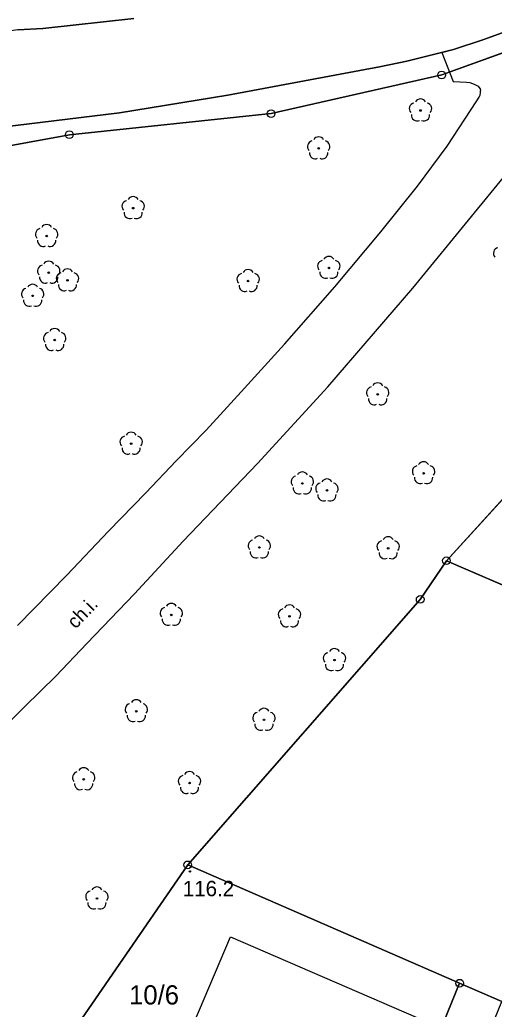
# Model space of a CAD drawing. Extents: x 6434771 to 6436222, y 5663454 to 5664782.
# Drawn here: x 6435621.2 to 6435652.1, y 5663799.7 to 5663864.1 of the extents above; entities that cross this region are included whole.
import ezdxf

# ---------------------------------------------------------------- set-up
doc = ezdxf.new("R2010")
doc.units = 0
for name, color, linetype in [('Warstwa 1', 7, 'Continuous'), ('Warstwa 10', 7, 'Continuous'), ('Warstwa 11', 7, 'Continuous'), ('Warstwa 13', 7, 'Continuous'), ('Warstwa 15', 7, 'Continuous'), ('Warstwa 18', 7, 'Continuous'), ('Warstwa 6', 7, 'Continuous'), ('Warstwa 8', 7, 'Continuous'), ('Warstwa 9', 7, 'Continuous')]:
    doc.layers.add(name, color=color, linetype=linetype)

msp = doc.modelspace()

# ---------------------------------------------------------------- linework, layer by layer
at = {"layer": 'Warstwa 1'}
for p, q in [((6435648.655, 5663860.497), (6435657.302, 5663863.623)), ((6435648.655, 5663860.497), (6435657.302, 5663863.623)), ((6435637.544, 5663857.981), (6435648.655, 5663860.497)), ((6435637.544, 5663857.981), (6435648.655, 5663860.497)), ((6435624.408, 5663856.609), (6435637.544, 5663857.981)), ((6435624.408, 5663856.609), (6435637.544, 5663857.981)), ((6435613.214, 5663854.564), (6435624.408, 5663856.609)), ((6435613.214, 5663854.564), (6435624.408, 5663856.609)), ((6435648.964, 5663828.871), (6435656.848, 5663837.517)), ((6435648.964, 5663828.871), (6435656.848, 5663837.517)), ((6435647.254, 5663826.352), (6435648.964, 5663828.871)), ((6435647.254, 5663826.352), (6435648.964, 5663828.871)), ((6435648.964, 5663828.871), (6435679.775, 5663815.599)), ((6435648.964, 5663828.871), (6435679.775, 5663815.599)), ((6435632.116, 5663809.073), (6435647.254, 5663826.352)), ((6435632.116, 5663809.073), (6435647.254, 5663826.352)), ((6435621.643, 5663793.868), (6435632.116, 5663809.073)), ((6435621.643, 5663793.868), (6435632.116, 5663809.073)), ((6435632.116, 5663809.073), (6435649.824, 5663801.369)), ((6435632.116, 5663809.073), (6435649.824, 5663801.369)), ((6435643.218, 5663785.168), (6435649.824, 5663801.369)), ((6435643.218, 5663785.168), (6435649.824, 5663801.369)), ((6435649.824, 5663801.369), (6435652.579, 5663800.176)), ((6435649.824, 5663801.369), (6435652.579, 5663800.176))]:
    msp.add_line(p, q, dxfattribs=at)
at = {"layer": 'Warstwa 10'}
for centre in [(6435648.655, 5663860.497), (6435637.544, 5663857.981), (6435624.408, 5663856.609), (6435648.964, 5663828.871), (6435648.964, 5663828.871), (6435647.254, 5663826.352), (6435647.254, 5663826.352), (6435632.116, 5663809.073), (6435632.116, 5663809.073), (6435649.824, 5663801.369)]:
    msp.add_circle(centre, 0.25, dxfattribs=at)
at = {"layer": 'Warstwa 11'}
for centre in [(6435647.275, 5663858.188), (6435640.643, 5663855.718), (6435628.562, 5663851.827), (6435622.931, 5663850.014), (6435641.308, 5663847.937), (6435623.064, 5663847.627), (6435624.285, 5663847.129), (6435636.049, 5663847.082), (6435622.019, 5663846.121), (6435623.454, 5663843.242), (6435644.487, 5663839.702), (6435628.431, 5663836.492), (6435647.474, 5663834.568), (6435639.581, 5663833.905), (6435641.18, 5663833.45), (6435636.78, 5663829.737), (6435645.169, 5663829.681), (6435631.048, 5663825.345), (6435638.746, 5663825.253), (6435641.672, 5663822.402), (6435628.769, 5663819.074), (6435637.081, 5663818.513), (6435625.342, 5663814.642), (6435632.235, 5663814.399), (6435626.203, 5663806.884)]:
    msp.add_circle(centre, 0.05, dxfattribs=at)
for centre, start, end in [((6435647.275, 5663858.563), 30.14713, 149.85287), ((6435646.918, 5663858.304), 102.14713, 221.85287), ((6435647.632, 5663858.304), 318.14713, 77.85287), ((6435647.055, 5663857.885), 174.14713, 293.85287), ((6435647.495, 5663857.885), 246.14713, 5.85287), ((6435640.286, 5663855.834), 102.14713, 221.85287), ((6435640.643, 5663856.093), 30.14713, 149.85287), ((6435641, 5663855.834), 318.14713, 77.85287), ((6435640.423, 5663855.415), 174.14713, 293.85287), ((6435640.863, 5663855.415), 246.14713, 5.85287), ((6435628.562, 5663852.202), 30.14713, 149.85287), ((6435628.205, 5663851.943), 102.14713, 221.85287), ((6435628.919, 5663851.943), 318.14713, 77.85287), ((6435628.342, 5663851.524), 174.14713, 293.85287), ((6435628.782, 5663851.524), 246.14713, 5.85287), ((6435622.574, 5663850.13), 102.14713, 221.85287), ((6435622.931, 5663850.389), 30.14713, 149.85287), ((6435623.288, 5663850.13), 318.14713, 77.85287), ((6435622.711, 5663849.711), 174.14713, 293.85287), ((6435623.151, 5663849.711), 246.14713, 5.85287), ((6435652.396, 5663848.88), 102.14713, 221.85287), ((6435641.308, 5663848.312), 30.14713, 149.85287), ((6435622.707, 5663847.743), 102.14713, 221.85287), ((6435623.064, 5663848.002), 30.14713, 149.85287), ((6435623.421, 5663847.743), 318.14713, 77.85287), ((6435624.285, 5663847.504), 30.14713, 149.85287), ((6435636.049, 5663847.457), 30.14713, 149.85287), ((6435640.951, 5663848.053), 102.14713, 221.85287), ((6435641.665, 5663848.053), 318.14713, 77.85287), ((6435622.844, 5663847.324), 174.14713, 293.85287), ((6435623.284, 5663847.324), 246.14713, 5.85287), ((6435623.928, 5663847.245), 102.14713, 221.85287), ((6435624.642, 5663847.245), 318.14713, 77.85287), ((6435635.692, 5663847.198), 102.14713, 221.85287), ((6435636.406, 5663847.198), 318.14713, 77.85287), ((6435641.088, 5663847.634), 174.14713, 293.85287), ((6435641.528, 5663847.634), 246.14713, 5.85287), ((6435621.662, 5663846.237), 102.14713, 221.85287), ((6435622.019, 5663846.496), 30.14713, 149.85287), ((6435622.376, 5663846.237), 318.14713, 77.85287), ((6435624.065, 5663846.826), 174.14713, 293.85287), ((6435624.505, 5663846.826), 246.14713, 5.85287), ((6435635.829, 5663846.779), 174.14713, 293.85287), ((6435636.269, 5663846.779), 246.14713, 5.85287), ((6435621.799, 5663845.818), 174.14713, 293.85287), ((6435622.239, 5663845.818), 246.14713, 5.85287), ((6435623.454, 5663843.617), 30.14713, 149.85287), ((6435623.097, 5663843.358), 102.14713, 221.85287), ((6435623.811, 5663843.358), 318.14713, 77.85287), ((6435623.234, 5663842.939), 174.14713, 293.85287), ((6435623.674, 5663842.939), 246.14713, 5.85287), ((6435644.13, 5663839.818), 102.14713, 221.85287), ((6435644.487, 5663840.077), 30.14713, 149.85287), ((6435644.844, 5663839.818), 318.14713, 77.85287), ((6435644.267, 5663839.399), 174.14713, 293.85287), ((6435644.707, 5663839.399), 246.14713, 5.85287), ((6435628.074, 5663836.608), 102.14713, 221.85287), ((6435628.431, 5663836.867), 30.14713, 149.85287), ((6435628.788, 5663836.608), 318.14713, 77.85287), ((6435628.211, 5663836.189), 174.14713, 293.85287), ((6435628.651, 5663836.189), 246.14713, 5.85287), ((6435647.117, 5663834.684), 102.14713, 221.85287), ((6435647.474, 5663834.943), 30.14713, 149.85287), ((6435647.831, 5663834.684), 318.14713, 77.85287), ((6435639.224, 5663834.021), 102.14713, 221.85287), ((6435639.581, 5663834.28), 30.14713, 149.85287), ((6435639.938, 5663834.021), 318.14713, 77.85287), ((6435647.254, 5663834.265), 174.14713, 293.85287), ((6435647.694, 5663834.265), 246.14713, 5.85287), ((6435639.361, 5663833.602), 174.14713, 293.85287), ((6435639.801, 5663833.602), 246.14713, 5.85287), ((6435640.823, 5663833.566), 102.14713, 221.85287), ((6435641.18, 5663833.825), 30.14713, 149.85287), ((6435641.537, 5663833.566), 318.14713, 77.85287), ((6435640.96, 5663833.147), 174.14713, 293.85287), ((6435641.4, 5663833.147), 246.14713, 5.85287), ((6435636.78, 5663830.112), 30.14713, 149.85287), ((6435645.169, 5663830.056), 30.14713, 149.85287), ((6435636.423, 5663829.853), 102.14713, 221.85287), ((6435637.137, 5663829.853), 318.14713, 77.85287), ((6435644.812, 5663829.797), 102.14713, 221.85287), ((6435645.526, 5663829.797), 318.14713, 77.85287), ((6435636.56, 5663829.434), 174.14713, 293.85287), ((6435637, 5663829.434), 246.14713, 5.85287), ((6435644.949, 5663829.378), 174.14713, 293.85287), ((6435645.389, 5663829.378), 246.14713, 5.85287), ((6435631.048, 5663825.72), 30.14713, 149.85287), ((6435638.746, 5663825.628), 30.14713, 149.85287), ((6435630.691, 5663825.461), 102.14713, 221.85287), ((6435631.405, 5663825.461), 318.14713, 77.85287), ((6435638.389, 5663825.369), 102.14713, 221.85287), ((6435639.103, 5663825.369), 318.14713, 77.85287), ((6435630.828, 5663825.042), 174.14713, 293.85287), ((6435631.268, 5663825.042), 246.14713, 5.85287), ((6435638.526, 5663824.95), 174.14713, 293.85287), ((6435638.966, 5663824.95), 246.14713, 5.85287), ((6435641.315, 5663822.518), 102.14713, 221.85287), ((6435641.672, 5663822.777), 30.14713, 149.85287), ((6435642.029, 5663822.518), 318.14713, 77.85287), ((6435641.452, 5663822.099), 174.14713, 293.85287), ((6435641.892, 5663822.099), 246.14713, 5.85287), ((6435628.412, 5663819.19), 102.14713, 221.85287), ((6435628.769, 5663819.449), 30.14713, 149.85287), ((6435629.126, 5663819.19), 318.14713, 77.85287), ((6435636.724, 5663818.629), 102.14713, 221.85287), ((6435637.081, 5663818.888), 30.14713, 149.85287), ((6435637.438, 5663818.629), 318.14713, 77.85287), ((6435628.549, 5663818.771), 174.14713, 293.85287), ((6435628.989, 5663818.771), 246.14713, 5.85287), ((6435636.861, 5663818.21), 174.14713, 293.85287), ((6435637.301, 5663818.21), 246.14713, 5.85287), ((6435624.985, 5663814.758), 102.14713, 221.85287), ((6435625.342, 5663815.017), 30.14713, 149.85287), ((6435625.699, 5663814.758), 318.14713, 77.85287), ((6435632.235, 5663814.774), 30.14713, 149.85287), ((6435625.122, 5663814.339), 174.14713, 293.85287), ((6435625.562, 5663814.339), 246.14713, 5.85287), ((6435631.878, 5663814.515), 102.14713, 221.85287), ((6435632.592, 5663814.515), 318.14713, 77.85287), ((6435632.015, 5663814.096), 174.14713, 293.85287), ((6435632.455, 5663814.096), 246.14713, 5.85287), ((6435625.846, 5663807), 102.14713, 221.85287), ((6435626.203, 5663807.259), 30.14713, 149.85287), ((6435626.56, 5663807), 318.14713, 77.85287), ((6435625.983, 5663806.581), 174.14713, 293.85287), ((6435626.423, 5663806.581), 246.14713, 5.85287)]:
    msp.add_arc(centre, 0.375, start, end, dxfattribs=at)
at = {"layer": 'Warstwa 13'}
msp.add_circle((6435632.257, 5663808.642), 0.045, dxfattribs=at)
at = {"layer": 'Warstwa 18'}
msp.add_lwpolyline([(6435634.9, 5663804.389), (6435646.987, 5663799.163), (6435642.821, 5663789.523), (6435630.793, 5663794.728), (6435634.9, 5663804.389)], dxfattribs=at)
at = {"layer": 'Warstwa 6'}
for points in [[(6435679.775, 5663815.599), (6435678.592, 5663812.843), (6435694.271, 5663806.083), (6435701.006, 5663803.181), (6435719.351, 5663795.279), (6435739.621, 5663841.649), (6435741.235, 5663845.289), (6435742.717, 5663848.762), (6435690.679, 5663871.692), (6435659.895, 5663840.59), (6435656.848, 5663837.517), (6435648.964, 5663828.871)], [(6435683.645, 5663781.479), (6435678.655, 5663769.939), (6435676.012, 5663763.81), (6435701.112, 5663753.066), (6435703.509, 5663758.567), (6435685.133, 5663766.44), (6435693.126, 5663784.935), (6435701.006, 5663803.181), (6435694.271, 5663806.083), (6435678.592, 5663812.843), (6435679.775, 5663815.599), (6435648.964, 5663828.871), (6435647.254, 5663826.352), (6435632.116, 5663809.073), (6435649.824, 5663801.369), (6435652.579, 5663800.176), (6435661.463, 5663796.308), (6435659.581, 5663791.981)], [(6435631.491, 5663789.529), (6435639.269, 5663786.095), (6435639.537, 5663786.742), (6435643.218, 5663785.168), (6435649.824, 5663801.369), (6435632.116, 5663809.073), (6435621.643, 5663793.868)], [(6435652.579, 5663800.176), (6435649.824, 5663801.369), (6435643.218, 5663785.168), (6435645.974, 5663783.984)]]:
    msp.add_lwpolyline(points, close=True, dxfattribs=at)
for points in [[(6435628.604, 5663864.173), (6435622.691, 5663863.532), (6435621.061, 5663863.448), (6435620.115, 5663863.317), (6435619.052, 5663863.129), (6435616.684, 5663862.619), (6435613.551, 5663861.881), (6435611.066, 5663861.257), (6435607.603, 5663860.254), (6435605.053, 5663859.435), (6435602.882, 5663858.558), (6435600.454, 5663857.408), (6435599.181, 5663856.791), (6435597.882, 5663856.083), (6435596.104, 5663855.065), (6435594.168, 5663853.791), (6435592.342, 5663852.486), (6435590.559, 5663851.101), (6435588.41, 5663849.282), (6435585.663, 5663846.949), (6435583.836, 5663845.265), (6435583.508, 5663845.088)], [(6435657.302, 5663863.623), (6435648.655, 5663860.497), (6435637.544, 5663857.981), (6435624.408, 5663856.609), (6435613.214, 5663854.564), (6435603.638, 5663850.779), (6435594.229, 5663844.972), (6435579.684, 5663831.466), (6435548.671, 5663800.788), (6435521.147, 5663772.588)], [(6435521.147, 5663772.588), (6435548.671, 5663800.788), (6435579.684, 5663831.466), (6435594.229, 5663844.972), (6435603.638, 5663850.779), (6435613.214, 5663854.564), (6435624.408, 5663856.609), (6435637.544, 5663857.981), (6435648.655, 5663860.497), (6435657.302, 5663863.623)], [(6435654.369, 5663863.901), (6435651.397, 5663862.812), (6435649.417, 5663862.157), (6435646.38, 5663861.401), (6435644.611, 5663861.031), (6435640.06, 5663860.179), (6435634.727, 5663859.174), (6435627.672, 5663858.042), (6435620.002, 5663857.1), (6435618.198, 5663856.858), (6435614.774, 5663856.152), (6435611.656, 5663855.305), (6435609.284, 5663854.518), (6435607.211, 5663853.75), (6435605.044, 5663852.8), (6435603.383, 5663851.959), (6435602.171, 5663851.307), (6435599.711, 5663849.9), (6435598.405, 5663849.043), (6435595.606, 5663847.066), (6435592.633, 5663844.827), (6435588.264, 5663841.158), (6435580.285, 5663833.741)], [(6435621.643, 5663793.868), (6435632.116, 5663809.073), (6435647.254, 5663826.352), (6435648.964, 5663828.871), (6435656.848, 5663837.517)]]:
    msp.add_lwpolyline(points, dxfattribs=at)
at = {"layer": 'Warstwa 8'}
for p, q in [((6435622.691, 5663863.532), (6435628.604, 5663864.173)), ((6435621.061, 5663863.448), (6435622.691, 5663863.532)), ((6435651.397, 5663862.812), (6435654.369, 5663863.901)), ((6435649.417, 5663862.157), (6435651.397, 5663862.812)), ((6435646.38, 5663861.401), (6435649.417, 5663862.157)), ((6435644.611, 5663861.031), (6435646.38, 5663861.401)), ((6435640.06, 5663860.179), (6435644.611, 5663861.031)), ((6435634.727, 5663859.174), (6435640.06, 5663860.179)), ((6435627.672, 5663858.042), (6435634.727, 5663859.174)), ((6435620.002, 5663857.1), (6435627.672, 5663858.042))]:
    msp.add_line(p, q, dxfattribs=at)
at = {"layer": 'Warstwa 9'}
for p, q in [((6435651.397, 5663862.812), (6435654.369, 5663863.901)), ((6435649.417, 5663862.157), (6435651.397, 5663862.812)), ((6435648.664, 5663861.97), (6435649.417, 5663862.157)), ((6435648.664, 5663861.97), (6435649.408, 5663860.069)), ((6435649.408, 5663860.069), (6435650.259, 5663860.036)), ((6435650.259, 5663860.036), (6435650.478, 5663859.998)), ((6435650.478, 5663859.998), (6435650.763, 5663859.903)), ((6435650.763, 5663859.903), (6435650.946, 5663859.82)), ((6435650.946, 5663859.82), (6435651.027, 5663859.776)), ((6435651.027, 5663859.776), (6435651.08, 5663859.715)), ((6435651.08, 5663859.715), (6435651.151, 5663859.598)), ((6435651.151, 5663859.598), (6435651.187, 5663859.489)), ((6435651.186, 5663859.351), (6435651.187, 5663859.489)), ((6435649.014, 5663855.853), (6435650.943, 5663858.809)), ((6435650.943, 5663858.809), (6435651.104, 5663859.046)), ((6435651.104, 5663859.046), (6435651.163, 5663859.189)), ((6435651.163, 5663859.189), (6435651.186, 5663859.351)), ((6435647.086, 5663853.255), (6435649.014, 5663855.853)), ((6435646.773, 5663846.626), (6435652.653, 5663853.811)), ((6435644.699, 5663850.276), (6435647.086, 5663853.255)), ((6435641.694, 5663846.7), (6435644.699, 5663850.276)), ((6435638.423, 5663842.972), (6435641.694, 5663846.7)), ((6435641.247, 5663840.197), (6435646.773, 5663846.626)), ((6435635.587, 5663839.866), (6435638.423, 5663842.972)), ((6435636.658, 5663835.209), (6435641.247, 5663840.197)), ((6435633.321, 5663837.377), (6435635.587, 5663839.866)), ((6435631.371, 5663835.373), (6435633.321, 5663837.377)), ((6435629.38, 5663833.289), (6435631.371, 5663835.373)), ((6435631.814, 5663830.153), (6435636.658, 5663835.209)), ((6435626.951, 5663830.795), (6435629.38, 5663833.289)), ((6435624.248, 5663827.936), (6435626.951, 5663830.795)), ((6435628.646, 5663826.714), (6435631.814, 5663830.153)), ((6435621.041, 5663824.651), (6435624.248, 5663827.936)), ((6435625.55, 5663823.48), (6435628.646, 5663826.714)), ((6435623.523, 5663821.362), (6435625.55, 5663823.48)), ((6435621.499, 5663819.382), (6435623.523, 5663821.362)), ((6435618.94, 5663816.856), (6435621.499, 5663819.382))]:
    msp.add_line(p, q, dxfattribs=at)

# ---------------------------------------------------------------- texts
at = {"layer": 'Warstwa 13'}
msp.add_text('116.2', height=1, dxfattribs=at).set_placement((6435631.794, 5663807.03))
at = {"layer": 'Warstwa 15'}
msp.add_text('10/6', height=1.25, dxfattribs=at).set_placement((6435628.296, 5663799.981))
at = {"layer": 'Warstwa 9'}
msp.add_text('ch.i.', height=0.9, rotation=46.24915, dxfattribs=at).set_placement((6435624.817, 5663824.39))

doc.saveas('drawing.dxf')
